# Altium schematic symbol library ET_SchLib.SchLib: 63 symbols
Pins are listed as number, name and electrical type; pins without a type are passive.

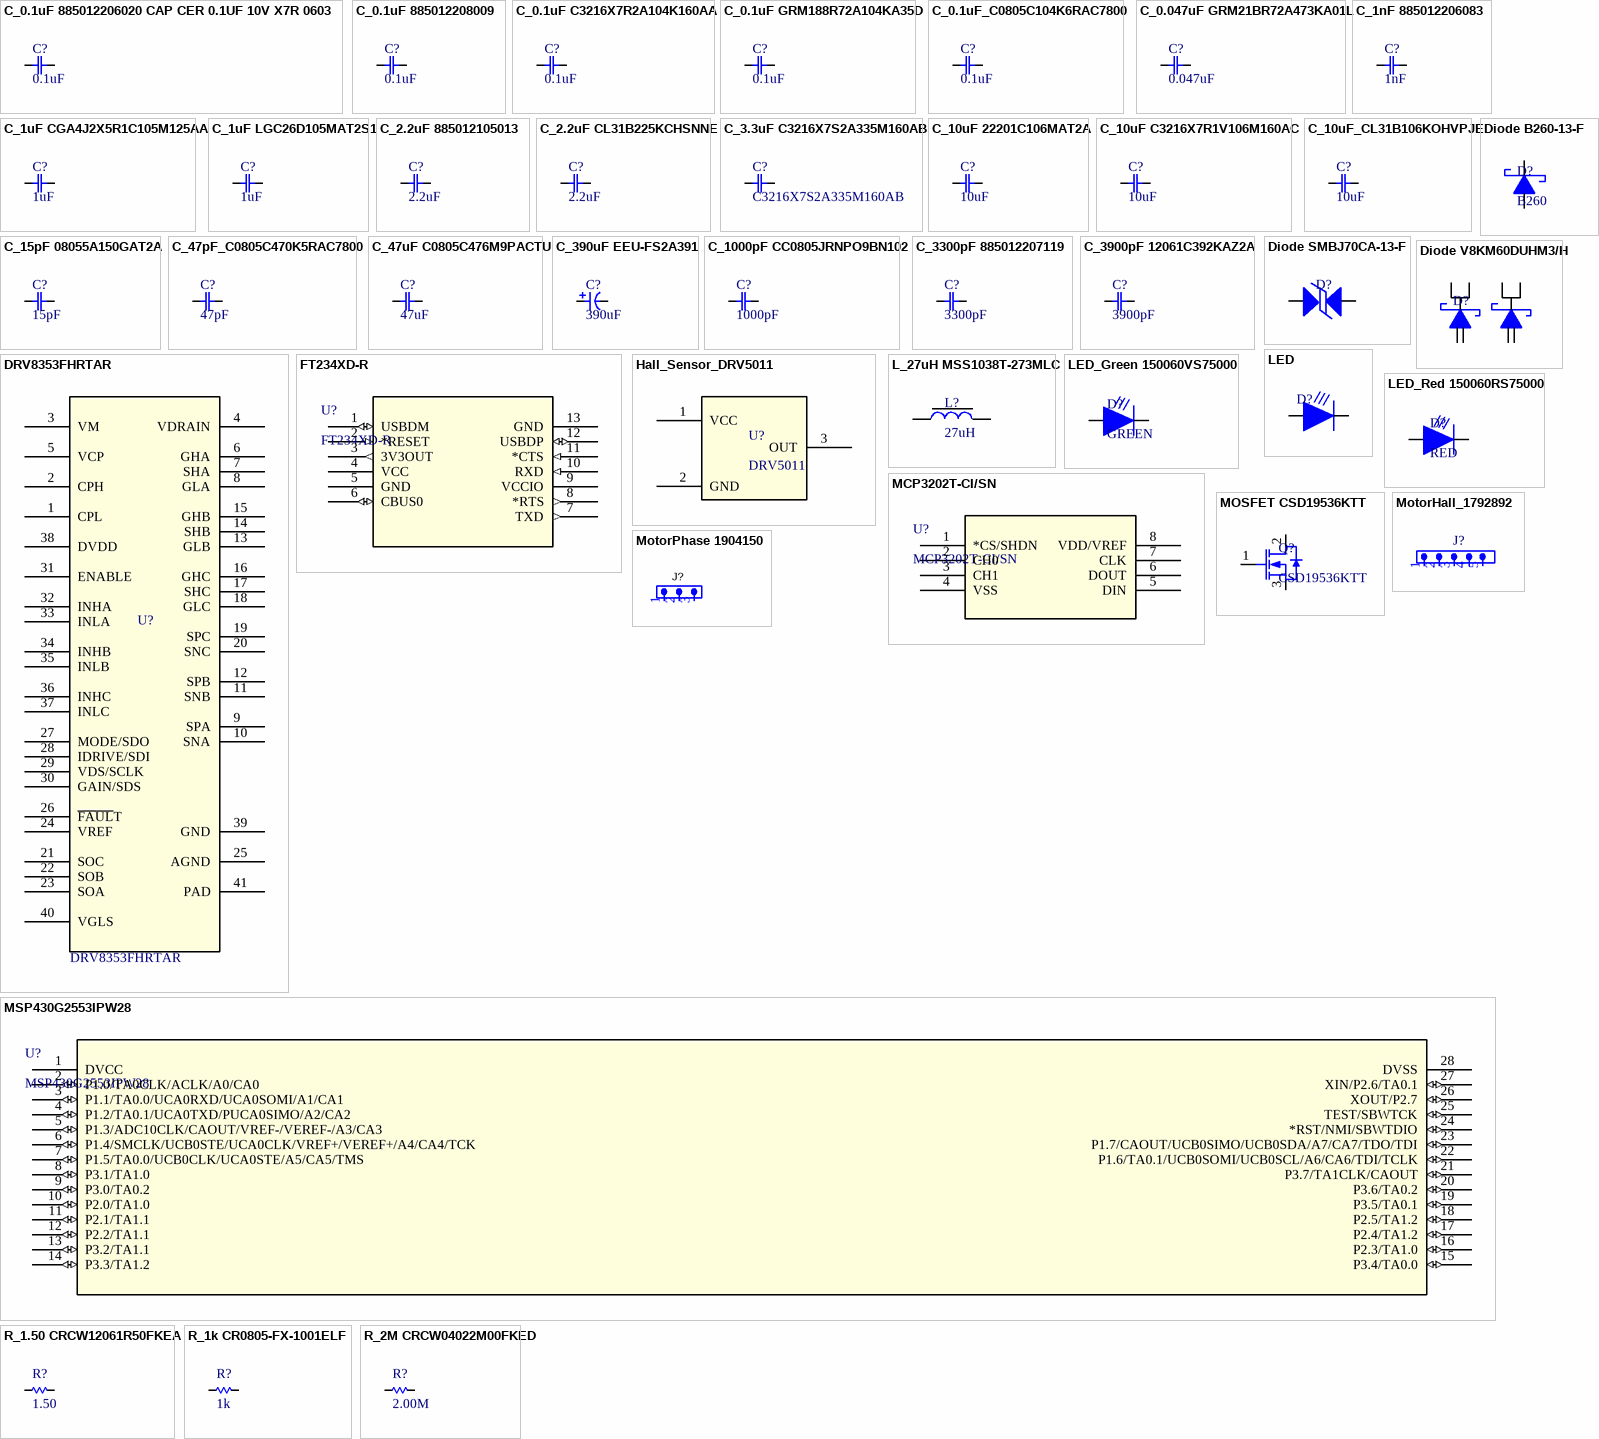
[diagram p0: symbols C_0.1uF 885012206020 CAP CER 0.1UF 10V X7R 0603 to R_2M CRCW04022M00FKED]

## C_0.1uF 885012206020 CAP CER 0.1UF 10V X7R 0603
designator C?, comment 0.1uF
CAP CER 0.1UF 10V X7R 0603; Manufacturer: TDK; Manufacturer Part Number: C3216X7R2A104K160AA; Capacitance: 100nF; Tolerance: 10%; Voltage Rating: 100V
footprint 1206 (1206 from SM-752 data)
pins: 1, 2

## C_0.1uF 885012208009
designator C?, comment 0.1uF
CAP CER 0.1UF 10V X7R 1206; Part Number: 885012208009
footprint 1206 (1206 from SM-752 data)
pins: 1, 2

## C_0.1uF C3216X7R2A104K160AA
designator C?, comment 0.1uF
CAP CER 0.1UF 100V X7R 1206; Manufacturer: TDK; Manufacturer Part Number: C3216X7R2A104K160AA; Capacitance: 100nF; Tolerance: 10%
footprint 1206 (1206 from SM-752 data)
pins: 1, 2

## C_0.1uF GRM188R72A104KA35D
designator C?, comment 0.1uF
0603 0.1 uF 100 V ±10 % Tolerance X7R SMT Multilayer Ceramic Capacitor; Manufacturer: Murata; Manufacturer Part Number: GRM188R72A104KA35D; Capacitance: 100nF; Tolerance: 10%; Voltage Rating: 100V
footprint 0603 (0603 from SM-752 data)
pins: 1, 2

## C_0.1uF_C0805C104K6RAC7800
designator C?, comment 0.1uF
CAP CER SMD 0805 .1UF 35V 10% X7
footprint 0805_HV (0805 with 30mil clearance between pads)
pins: 1, 2

## C_0.047uF GRM21BR72A473KA01L
designator C?, comment 0.047uF
Cap Ceramic 0.047uF 100V X7R 10% SMD 0805 125C Embossed T/R; Manufacturer: Murata; Manufacturer Part Number: GRM21BR72A473KA01L; Capacitance: 47nF
footprint 0805_HV (0805 with 30mil clearance between pads)
pins: 1, 2

## C_1nF 885012206083
designator C?, comment 1nF
CAP, CERM, 1000 pF, 50 V,+/- 10%, X7R, 0603
footprint 0603 (0603 from SM-752 data)
pins: 1, 2

## C_1uF CGA4J2X5R1C105M125AA
designator C?, comment 1uF
1 µF ±20% 16V Ceramic Capacitor X5R 0805 (2012 Metric); Part Number: CGA4J2X5R1C105M125AA
footprint 0805_HV (0805 with 30mil clearance between pads)
pins: 1, 2

## C_1uF LGC26D105MAT2S1
designator C?, comment 1uF
CAP CER 1UF 6.3V X5R 0805; Part Number: LGC26D105MAT2S1
footprint 0805_HV (0805 with 30mil clearance between pads)
pins: 1, 2

## C_2.2uF 885012105013
designator C?, comment 2.2uF
Cap, 2.2UF, 10V, 20%, X5R, 0402; Manufacturer: Wurth Electronics; Manufacturer Part Number: 885012105013
footprint 0402 (0402 from SM-752 data)
pins: 1, 2

## C_2.2uF CL31B225KCHSNNE
designator C?, comment 2.2uF
Cap Ceramic 2.2uF 100V X7R 10% Pad SMD 1206 Soft Termination 125C T/R; Manufacturer: Samsung; Manufacturer Part Number: CL31B225KCHSNNE
footprint 1206 (1206 from SM-752 data)
pins: 1, 2

## C_3.3uF C3216X7S2A335M160AB
designator C?, comment C3216X7S2A335M160AB
Cap Ceramic 3.3uF 100V X7S 20% SMD 1206 125C Plastic T/R; Manufacturer: TDK
footprint 1206_190
pins: 1, 2

## C_10uF 22201C106MAT2A
designator C?, comment 10uF
Cap Ceramic 10uF 100V X7R 20% SMD 2220 125°C Embossed T/R; Manufacturer: Kyocera AVX; Manufacturer Part Number: 22201C106MAT2A; Number of Outputs: 1; Output Voltage: 58V; Output Current: 1.5A; Switching Frequency: 581kHz; Max Input Voltage: 60V; Min Input Voltage: 3.5V; Synchronous Rectifier: No; Min Output Voltage: 800mV; Quiescent Current: 116uA; Output Type: Adjustable; Topology: Buck-Boost
footprint 2220_280 (Chip Capacitor, Body 5.7x5.0mm, IPC Medium Density)
pins: 1, 2

## C_10uF C3216X7R1V106M160AC
designator C?, comment 10uF
CERAMIC CAPACITOR, 10UF, 35V, X7R, 1206, FULL REEL; Product Range:C Series; Capacitance:10 F; Capacitance Tolerance: 20%; Dielectric Characteristic:X7R; Voltage Rating:35V; Ceramic Capacitor Case:1206 [3216 Metric]; MSL:- ;RoHS Compliant: Yes; Manufacturer: TDK; Manufacturer Part Number: C3216X7R1V106M160AC
footprint 1206_190
pins: 1, 2

## C_10uF_CL31B106KOHVPJE
designator C?, comment 10uF
MLCC10UF16V 10 X7R1206; Manufacturer: TDK; Manufacturer Part Number: C3216X7R1V106M160AC; Dielectric Material: Ceramic; Voltage Rating: 35V; Tolerance: 20%; Dielectric: X7R
footprint 1206_190
footprint 1206 (1206 from SM-752 data)
pins: 1, 2

## C_15pF 08055A150GAT2A
designator C?, comment 15pF
Capacitor, ceramic, 15Pf, 50Vdc, 2-% Tol, 2+% Tol, c0G-Tc Code, -30, 30Ppm-Tc Rohs Compliant: Yes; Manufacturer: Kyocera AVX; Manufacturer Part Number: 08055A150GAT2A; Tolerance: 2%; Dielectric: C0G; Voltage Rating: 50V
footprint 0805_HV (0805 with 30mil clearance between pads)
pins: 1, 2

## C_47pF_C0805C470K5RAC7800
designator C?, comment 47pF
CAP CER 47PF 50V X7R 0805; Manufacturer: Samsung; Manufacturer Part Number: CL05A105MO5NNNC; Capacitance: 1uF; Tolerance: 20%; Voltage Rating: 16V
footprint 0805_HV (0805 with 30mil clearance between pads)
pins: 1, 2

## C_47uF C0805C476M9PACTU
designator C?, comment 47uF
Cap Ceramic 47uF 6.3V X5R 20% SMD 0805 Plastic T/R; Manufacturer: KEMET; Manufacturer Part Number: C0805C476M9PACTU; Dissipation Factor: 5%
footprint 0805_HV (0805 with 30mil clearance between pads)
pins: 1, 2

## C_390uF EEU-FS2A391
designator C?, comment 390uF
CAP ALUM 390UF 20% 100V THRUHOLE; Manufacturer: Panasonic; Manufacturer Part Number: EEU-FS2A391
footprint YXJ_1600x2500 (TH, 2-Leads, Dia 16mm, Pin Spacing 7.5mm)
pins: 1, 2

## C_1000pF CC0805JRNPO9BN102
designator C?, comment 1000pF
Capacitor 1NF 50V 0805 SMD Npo (reel); Manufacturer: Yageo; Manufacturer Part Number: CC0805JRNPO9BN102; Dielectric Material: Ceramic; Tolerance: 5%; Dielectric: C0G; Insulation Resistance: 10GR; Temperature Coefficient: 30ppm/°C; Dissipation Factor: 0.1%
footprint 0805_HV (0805 with 30mil clearance between pads)
pins: 1, 2

## C_3300pF 885012207119
designator C?, comment 3300pF
Cap, 3300PF, 100V, 10%, X7R, 0805; Manufacturer: Wurth Electronics; Manufacturer Part Number: 885012207119; Capacitance: 3.3nF
footprint 0805_HV (0805 with 30mil clearance between pads)
pins: 1, 2

## C_3900pF 12061C392KAZ2A
designator C?, comment 3900pF
CAP CER 3900PF 100V X7R 1206
footprint 1206 (1206 from SM-752 data)
pins: 1, 2

## Diode B260-13-F
designator D?, comment B260
Diode Schottky 60V 2A 2-Pin SMB T/R Diode Schottky 60V 2A 2-Pin SMB T/R; Manufacturer: Diodes; Manufacturer Part Number: B260-13-F; Element Configuration: Single; Max Reverse Current: 500uA; Peak Non-Repetitive Surge Current: 50A; Forward Voltage: 700mV; Polarity: Standard; Capacitance: 200pF
pins: 1, 2

## Diode SMBJ70CA-13-F
designator D?, comment SMBJ70CA-13-F  (value not drawn)
Diode TVS Single Bi-Dir 70V 600W 2-Pin SMB T/R; Manufacturer: Diodes; Manufacturer Part Number: SMBJ7.0CA-13-F; Number of Terminals/Pins: 2; Package Body Material: Plastic; Diode Element Material: SILICON; Min Breakdown Voltage: 77.8V; Clamping Voltage: 113V; Peak Pulse Current: 5.3A; Direction: Bidirectional; Max Reverse Leakage Current: 5uA; Test Current: 1mA; Max Breakdown Voltage: 89.5V; Reverse Breakdown Voltage: 7.78V; Number of Elements: 1; Power Line Protection: No; Leakage Current: 400uA; Voltage Rating (DC): 7V; Diode Type: ZENER; Time @ Peak Reflow Temperature-Max (s): 5s
footprint SMB-Bi (Molded Diode, 2-Leads, Body 5.4x3.6mm, IPC Medium Density, based on OnSemi component dimensions)
pins: 1, 2

## Diode V8KM60DUHM3/H
designator D?, comment V8KM60DUHM3/H  (value not drawn)
Diode Array 2 Independent Schottky 60 V 8A Surface Mount 8-PowerTDFN
footprint V8KM60DUHM3/H
pins: 1, 2, 3, 4, 5, 6, 7, 8

## DRV8353FHRTAR
designator U?
footprint DRV8353FHRTAR (QFN, 40-Leads, Body 6.00x6.00mm, Pitch 0.50mm, Thermal Pad 4.15x4.15mm, IPC Medium Density)
pins: 1 CPL, 2 CPH, 3 VM, 4 VDRAIN, 5 VCP, 6 GHA, 7 SHA, 8 GLA, 9 SPA, 10 SNA, 11 SNB, 12 SPB, 13 GLB, 14 SHB, 15 GHB, 16 GHC, 17 SHC, 18 GLC, 19 SPC, 20 SNC, 21 SOC, 22 SOB, 23 SOA, 24 VREF, 25 AGND, 26 ~{FAUL}T, 27 MODE/SDO, 28 IDRIVE/SDI, 29 VDS/SCLK, 30 GAIN/SDS, 31 ENABLE, 32 INHA, 33 INLA, 34 INHB, 35 INLB, 36 INHC, 37 INLC, 38 DVDD, 39 GND, 40 VGLS, 41 PAD

## FT234XD-R
designator U?
IC USB SERIAL BASIC UART 12DFN; Mfr_Name: FTDI, Future Technology Devices International Ltd
footprint DFN-12_FTD
footprint FT234XD-R
pins: 1 USBDM (io), 2 *RESET (in), 3 3V3OUT (out), 4 VCC (power), 5 GND (power), 6 CBUS0 (io), 7 TXD (out), 8 *RTS (out), 9 VCCIO (power), 10 RXD (in), 11 *CTS (in), 12 USBDP (io), 13 GND (power)

## Hall_Sensor_DRV5011
designator U?, comment DRV5011
MAGNETIC SWITCH LATCH TO92-3
footprint Hall_sensor
footprint Hall_sensor
pins: 1 VCC, 2 GND, 3 OUT

## L_27uH MSS1038T-273MLC
designator L?, comment 27uH
Power inductor, shielded, 10/20/30% tol, SMT, RoHS; Manufacturer: Coilcraft; Manufacturer Part Number: MSS1038T-273MLC; Core Material: Ferrite; Inductance Tolerance: 20%; Self Resonant Frequency: 15MHz; Max DC Current: 2.35A; DC Resistance (DCR): 89mR; Test Frequency: 100kHz; Saturation Current: 1.98A
footprint MSS1038T-273MLC (Coilcraft Shielded Power Inductors)
pins: 1, 2

## LED
designator D?  (value not drawn)
footprint LED_TH
pins: 1, 2

## LED_Green 150060VS75000
designator D?, comment GREEN
Led, Green, 570 Nm, 2 V, 30 Ma, 40 Mcd Rohs Compliant: Yes; Manufacturer: Wurth Electronics; Manufacturer Part Number: 150060VS75000; Luminous Intensity: 40mcd; Viewing Angle: 140°; Forward Voltage: 2V; Wavelength: 570nm; Lens Style: Clear,Rectangular; Forward Current: 30mA; Test Current: 20mA
footprint WL-SMCW_GREEN (WURTH)
pins: 1, 2

## LED_Red 150060RS75000
designator D?, comment RED
LED Low-Power Uni-Color Red 630nm 2V 2-Pin Chip 0603(1608Metric) T/R; Manufacturer: Wurth Electronics; Manufacturer Part Number: 150060RS75000; Viewing Angle: 140°; Lens Style: Clear,Rectangular; Luminous Intensity: 250mcd; Forward Current: 30mA; Wavelength: 625nm; Test Current: 20mA
footprint WL-SMCW_GREEN (WURTH)
pins: 1, 2

## MCP3202T-CI/SN
designator U?
IC ADC 12BIT SAR 8SOIC; Mfr_Name: Microchip
footprint SOIC8-N_MC_MCH
footprint MCP3202T-CI/SN (SOIC, 8-Leads, Body 4.90x3.90mm, Pitch 1.27mm, IPC Medium Density)
pins: 1 *CS/SHDN, 2 CH0, 3 CH1, 4 VSS, 5 DIN, 6 DOUT, 7 CLK, 8 VDD/VREF

## MOSFET CSD19536KTT
designator Q?, comment CSD19536KTT
This 100 V, 2.0 m D2PAK (TO-263) NexFET power MOSFET is designed to minimize losses in power conversion applications.; Manufacturer: Texas Instruments; Drain to Source Voltage (Vdss): 100V; Continuous Drain Current (ID): 200A; Rds On Max: 2.4mR; Input Capacitance: 12nF; Max Power Dissipation: 375W; Fall Time: 6ns; Gate to Source Voltage (Vgs): 20V; Rise Time: 8ns; Turn-On Delay Time: 13ns; Turn-Off Delay Time: 32ns; Element Configuration: Single
footprint KTT0002A (TO-263-2)
pins: 1, 2, 3

## MotorHall_1792892
designator J?
Wire-To-Board Terminal Block, 5, 400 V, 12 A, 26 Awg, 14 Awg, 2.5 Mm Rohs Compliant: Yes; Manufacturer: Phoenix Contact; Manufacturer Part Number: 1792892; Current Rating: 10A; Voltage Rating: 300V; Number of Contacts: 5; Number of Levels: 1; Wire Gauge (Max): 26AWG; Wire Gauge (Min): 14AWG; Pitch: 5mm; Stripping Length: 8mm; Approvals: VDE,cULus,CB,EAC
footprint MotorHall_1792892
pins: 1 0, 2, 3, 4, 5

## MotorPhase 1904150
designator J?  (value not drawn)
Conn PC Terminal Block 3 POS 9.52mm Solder ST Thru-Hole 32A; Manufacturer: Phoenix Contact; Manufacturer Part Number: 1904150; Number of Positions: 3; Gender: Male; Voltage Rating: 1kV; Number of Levels: 1; Current: 30A; Voltage: 600V; Max Supply Voltage: 800V; Wire Gauge (Max): 30AWG; Wire Gauge (Min): 10AWG; Wire/Cable Gauge: 24AWG; Approvals: CB
footprint MotorPhase 1904150
pins: 1 0, 2, 3

## MSP430G2553IPW28
designator U?
No Description Available; Mfr_Name: Texas Instruments
footprint PW28
pins: 1 DVCC (power), 2 P1.0/TA0CLK/ACLK/A0/CA0 (io), 3 P1.1/TA0.0/UCA0RXD/UCA0SOMI/A1/CA1 (io), 4 P1.2/TA0.1/UCA0TXD/PUCA0SIMO/A2/CA2 (io), 5 P1.3/ADC10CLK/CAOUT/VREF-/VEREF-/A3/CA3 (io), 6 P1.4/SMCLK/UCB0STE/UCA0CLK/VREF+/VEREF+/A4/CA4/TCK (io), 7 P1.5/TA0.0/UCB0CLK/UCA0STE/A5/CA5/TMS (io), 8 P3.1/TA1.0 (io), 9 P3.0/TA0.2 (io), 10 P2.0/TA1.0 (io), 11 P2.1/TA1.1 (io), 12 P2.2/TA1.1 (io), 13 P3.2/TA1.1 (io), 14 P3.3/TA1.2 (io), 15 P3.4/TA0.0 (io), 16 P2.3/TA1.0 (io), 17 P2.4/TA1.2 (io), 18 P2.5/TA1.2 (io), 19 P3.5/TA0.1 (io), 20 P3.6/TA0.2 (io), 21 P3.7/TA1CLK/CAOUT (io), 22 P1.6/TA0.1/UCB0SOMI/UCB0SCL/A6/CA6/TDI/TCLK (io), 23 P1.7/CAOUT/UCB0SIMO/UCB0SDA/A7/CA7/TDO/TDI (io), 24 *RST/NMI/SBWTDIO (io), 25 TEST/SBWTCK (io), 26 XOUT/P2.7 (io), 27 XIN/P2.6/TA0.1 (io), 28 DVSS (power)

## R_1.50 CRCW12061R50FKEA
designator R?, comment 1.50
Thick Film Resistors - SMD 1/4watt 1.5ohms 1%; Manufacturer: Vishay Dale; Manufacturer Part Number: CRCW12061R50FKEA; Resistance: 1.5R; Temperature Coefficient: 100ppm/°C; Power Rating: 250mW; Voltage Rating: 200V
footprint 1206 (1206 from SM-752 data)
pins: 1, 2

## R_1k CR0805-FX-1001ELF
designator R?, comment 1k
Res Thick Film 0805 1K Ohm 1% 1/8W ±100ppm/°C Molded SMD SMD Paper Tape on Plastic Reel; Manufacturer: Bourns; Manufacturer Part Number: CR0805-FX-1001ELF; Resistance: 1kR; Power Rating: 125mW; Voltage Rating: 150V
footprint 0805_HV (0805 with 30mil clearance between pads)
pins: 1, 2

## R_2M CRCW04022M00FKED
designator R?, comment 2.00M
Res Thick Film 0402 2M Ohm 1% 1/16W ±100ppm/°C Molded SMD SMD Paper T/R; Manufacturer: Vishay; Manufacturer Part Number: CRCW04022M00FKED; Resistance: 2MR; Power Rating: 63mW; Voltage Rating: 50V
footprint 0402 (0402 from SM-752 data)
pins: 1, 2

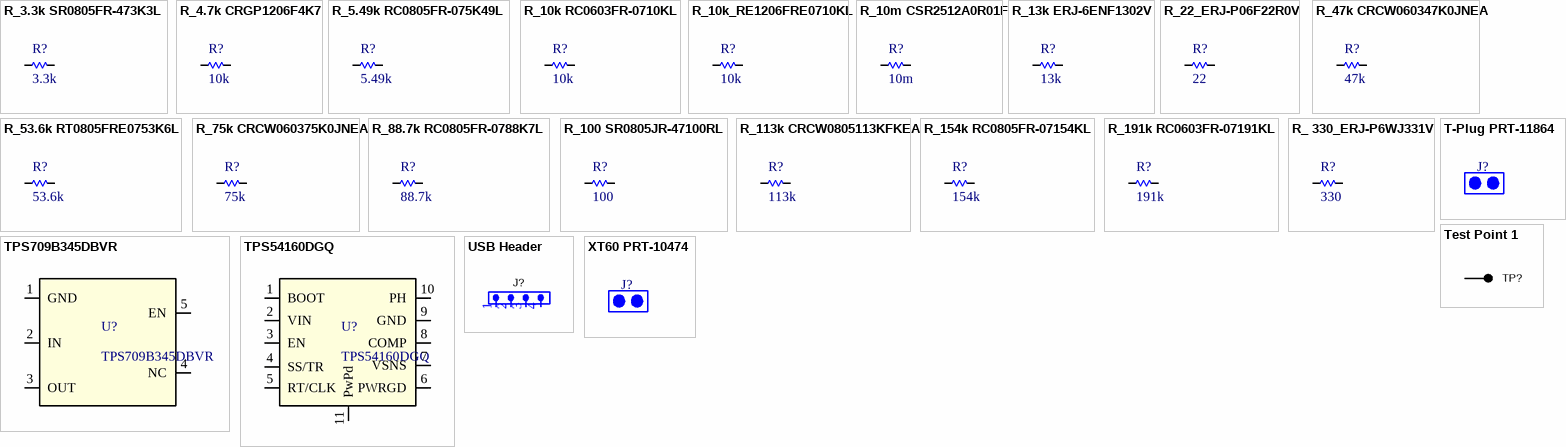
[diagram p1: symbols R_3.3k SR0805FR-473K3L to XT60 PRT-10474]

## R_3.3k SR0805FR-473K3L
designator R?, comment 3.3k
Res Thick Film 0805 3.3K Ohm 1% 0.5W(1/2W) ±100ppm/°C Pad SMD Automotive T/R; Manufacturer: Yageo; Manufacturer Part Number: SR0805FR-473K3L
footprint 0805_HV (0805 with 30mil clearance between pads)
pins: 1, 2

## R_4.7k CRGP1206F4K7
designator R?, comment 10k
RES 4.7K OHM 1% 1/2W 1206; Manufacturer: Panasonic; Manufacturer Part Number: ERJ-2RKF1002X; Resistance: 10kR; Temperature Coefficient: 100ppm/°C; Power Rating: 100mW; Voltage Rating: 50V
footprint 1206 (1206 from SM-752 data)
pins: 1, 2

## R_5.49k RC0805FR-075K49L
designator R?, comment 5.49k
Res Thick Film 2.0 x 1.2 mm 5.49K Ohm 1% 0.125W(1/8W) 100ppm/ C Molded SMD Paper T/R; Manufacturer: Yageo; Manufacturer Part Number: RC0805FR-075K49L; Power Rating: 125mW; Resistance: 5.49kR; Voltage Rating: 150V; Temperature Coefficient: 100ppm/°C
footprint 0805_HV (0805 with 30mil clearance between pads)
pins: 1, 2

## R_10k RC0603FR-0710KL
designator R?, comment 10k
RES 10K OHM 1% 1/10W 0603; Part Number: RC0603FR-0710KL
footprint 0603 (0603 from SM-752 data)
pins: 1, 2

## R_10k_RE1206FRE0710KL
designator R?, comment 10k
RES SMD 10K OHM 1% 1/4W 1206; Manufacturer: Vishay; Manufacturer Part Number: CRCW060347K0JNEA; Resistance: 47kR; Tolerance: 5%; Temperature Coefficient: 200ppm/°C; Max Power Dissipation: 100mW; Voltage Rating: 75V
footprint 1206 (1206 from SM-752 data)
pins: 1, 2

## R_10m CSR2512A0R01F
designator R?, comment 10m
Res 2512 0.01 Ohm 1% 2W ±50/±75ppm/C Pad SMD T/R; Manufacturer: Riedon; Manufacturer Part Number: CSR2512A0R01F; Resistance: 10mR; Temperature Coefficient: 50ppm/°C
footprint 2512 (Chip Resistor, 2-Leads, Body 6.40x3.20mm, IPC Medium Density)
pins: 1, 2

## R_13k ERJ-6ENF1302V
designator R?, comment 13k
Res Thick Film 0805 13K Ohm 1% 1/8W ±100ppm/°C Molded SMD Punched Carrier T/R; Manufacturer: Panasonic; Manufacturer Part Number: ERJ-6ENF1302V; Resistance: 13kR; Power Rating: 125mW; Voltage Rating: 150V
footprint 0805_HV (0805 with 30mil clearance between pads)
pins: 1, 2

## R_22_ERJ-P06F22R0V
designator R?, comment 22
RES SMD 22 OHM 1% 1/2W 0805; Manufacturer: Vishay; Manufacturer Part Number: CRCW060347K0JNEA; Resistance: 47kR; Tolerance: 5%; Temperature Coefficient: 200ppm/°C; Max Power Dissipation: 100mW; Voltage Rating: 75V
footprint 0805_HV (0805 with 30mil clearance between pads)
pins: 1, 2

## R_47k CRCW060347K0JNEA
designator R?, comment 47k
Res Thick Film 0603 47K Ohm 5% 1/10W ±200ppm/°C Molded SMD SMD Paper T/R; Manufacturer: Vishay; Manufacturer Part Number: CRCW060347K0JNEA; Resistance: 47kR; Max Power Dissipation: 100mW; Voltage Rating: 75V
footprint 0603 (0603 from SM-752 data)
pins: 1, 2

## R_53.6k RT0805FRE0753K6L
designator R?, comment 53.6k
High Precision-High Stability Chip Resistor Thin Film 0805 53.6kOhm 1% Paper T/R; Manufacturer: Yageo; Manufacturer Part Number: RT0805FRE0753K6L; Resistance: 53.6kR; Power Rating: 125mW; Voltage Rating: 150V; Temperature Coefficient: 50ppm/°C
footprint 0805_HV (0805 with 30mil clearance between pads)
pins: 1, 2

## R_75k CRCW060375K0JNEA
designator R?, comment 75k
Res Thick Film 0603 75K Ohm 5% 1/10W ±200ppm/°C Molded SMD SMD Paper T/R; Manufacturer: Vishay Dale; Manufacturer Part Number: CRCW060375K0JNEA; Resistance: 75kR; Max Power Dissipation: 100mW; Voltage Rating: 75V
footprint 0603 (0603 from SM-752 data)
pins: 1, 2

## R_88.7k RC0805FR-0788K7L
designator R?, comment 88.7k
Res Thick Film 0805 88.7K Ohm 1% 0.125W(1/8W) ±100ppm/C Pad SMD T/R; Manufacturer: Yageo; Manufacturer Part Number: RC0805FR-0788K7L; Resistance: 88.7kR; Power Rating: 125mW; Voltage Rating: 150V; Temperature Coefficient: 100ppm/°C
footprint 0805_HV (0805 with 30mil clearance between pads)
pins: 1, 2

## R_100 SR0805JR-47100RL
designator R?, comment 100
Res Thick Film 0805 100 Ohm 5% 0.5W(1/2W) ±100ppm/C Pad SMD Automotive T/R; Manufacturer: Yageo; Manufacturer Part Number: SR0805JR-47100RL
footprint 0805_HV (0805 with 30mil clearance between pads)
pins: 1, 2

## R_113k CRCW0805113KFKEA
designator R?, comment 113k
Res Thick Film 0805 113K Ohm 1% 1/8W ±100ppm/°C Molded SMD SMD Paper T/R; Manufacturer: Vishay; Manufacturer Part Number: CRCW0805113KFKEA; Resistance: 113kR; Max Power Dissipation: 125mW; Voltage Rating: 150V
footprint 0805_HV (0805 with 30mil clearance between pads)
pins: 1, 2

## R_154k RC0805FR-07154KL
designator R?, comment 154k
Res Thick Film 2.0 x 1.2 mm 154K Ohm 1% 0.125W(1/8W) 100ppm/ C Molded SMD Paper T/R; Manufacturer: Yageo; Manufacturer Part Number: RC0805FR-07154KL; Resistance: 154kR; Temperature Coefficient: 100ppm/°C; Power Rating: 125mW; Voltage Rating: 150V
footprint 0805_HV (0805 with 30mil clearance between pads)
pins: 1, 2

## R_191k RC0603FR-07191KL
designator R?, comment 191k
RES 191K OHM 1% 1/10W 0603; Part Number: RC0603FR-07191KL
footprint 0603 (0603 from SM-752 data)
pins: 1, 2

## R_ 330_ERJ-P6WJ331V
designator R?, comment 330
330 Ohms ±1% 0.5W, 1/2W Chip Resistor 0805 (2012 Metric) Automotive AEC-Q200, Pulse Withstanding Thick Film
footprint 0805_HV (0805 with 30mil clearance between pads)
pins: 1, 2

## T-Plug PRT-11864
designator J?
Deans Connector - M/f Pair; Manufacturer: SparkFun; Manufacturer Part Number: PRT-11864
pins: 1, 2

## Test Point 1
designator TP?  (no BOM)
Test Point, Round, Surface Pad
footprint TP200_SMD (Test Point, Single Side Land,2.00mm Land SMD)
pins: 1

## TPS709B345DBVR
designator U?
Voltage Regulator with Enable 3.45V 150mA 1uA IQ 5-Pin SOT-23 T/R; Manufacturer: Texas Instruments
footprint TPS709B345DBVR (SOT23, 5-Leads, Body 2.90x2.80mm, Pitch 0.95mm, IPC Medium Density)
pins: 1 GND, 2 IN, 3 OUT, 4 NC, 5 EN

## TPS54160DGQ
designator U?
3.5V to 60V Input, 1.5A Step-Down Converter with Eco-Mode 10-HVSSOP -40 to 150; Manufacturer: Texas Instruments; Number of Outputs: 1; Output Voltage: 58V; Switching Frequency: 581kHz; Synchronous Rectifier: No; Min Output Voltage: 800mV; Quiescent Current: 116uA; Output Type: Adjustable; Topology: Buck-Boost
footprint TPS54160DGQ
pins: 1 BOOT, 2 VIN, 3 EN, 4 SS/TR, 5 RT/CLK, 6 PWRGD, 7 VSNS, 8 COMP, 9 GND, 10 PH, 11 PwPd

## USB Header
designator J?  (value not drawn)
2.54mm pitch, 1mm hole; Manufacturer: Phoenix Contact; Manufacturer Part Number: 1904150; Number of Positions: 3; Gender: Male; Max Current Rating: 32A; Voltage Rating: 1kV; Number of Levels: 1; Current: 30A; Voltage: 600V; Max Supply Voltage: 800V; Pitch: 9.52mm; Wire Gauge (Max): 30AWG; Wire Gauge (Min): 10AWG; Wire/Cable Gauge: 24AWG; Approvals: CB
footprint USB Header (1x4 Header, Through Hole, Vertical)
pins: 1 0, 2, 3, 4

## XT60 PRT-10474
designator J?  (value not drawn)
XT60 Connectors Male/female Pair; Manufacturer: SparkFun; Manufacturer Part Number: PRT-10474
footprint XT60 PRT-10474
pins: 1, 2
